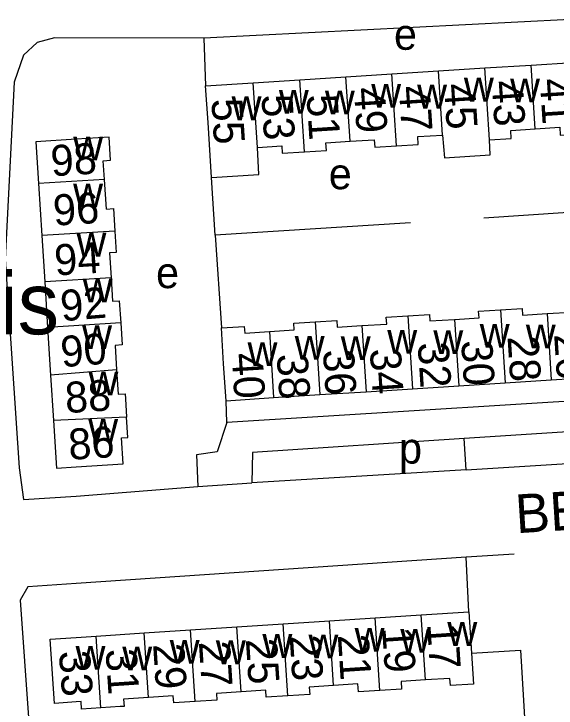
# Model space of a CAD drawing. Extents: x 159675 to 162108, y 386471 to 388472.
# Drawn here: x 160492 to 160562.1, y 387933.8 to 388023.5 of the extents above; entities that cross this region are included whole.
import ezdxf

# ---------------------------------------------------------------- set-up
doc = ezdxf.new("R2010")
doc.units = 0
for name, color, linetype in [('BLT_Basislijn', 7, 'Continuous'), ('BLT_Bebouwing', 7, 'Continuous'), ('BLT_Bebouwing_beschrifting', 7, 'Continuous'), ('BLT_Centroide', 7, 'Continuous'), ('BLT_Huisnummer', 7, 'Continuous'), ('BLT_Huisnummer_ tussenligend', 7, 'Continuous'), ('BLT_Onderverdeling_panden', 7, 'Continuous'), ('BLT_Straatnaam', 7, 'Continuous')]:
    doc.layers.add(name, color=color, linetype=linetype)

msp = doc.modelspace()

# ---------------------------------------------------------------- linework, layer by layer
at = {"layer": 'BLT_Basislijn'}
for p, q in [((160516.527, 388020.386), (160516.759, 388014.218)), ((160517.966, 387994.901), (160517.519, 388002.377)), ((160543.241, 387996.536), (160517.966, 387994.901)), ((160517.966, 387994.901), (160518.786, 387982.927)), ((160519.477, 387970.7), (160519.388, 387973.52)), ((160581.004, 387970.587), (160550.172, 387968.626)), ((160550.439, 387964.578), (160550.172, 387968.626)), ((160550.439, 387964.578), (160581.004, 387966.488)), ((160550.439, 387964.578), (160522.746, 387962.911)), ((160515.732, 387962.44), (160522.746, 387962.911)), ((160556.658, 387953.682), (160550.452, 387953.281)), ((160550.779, 387946.21), (160550.452, 387953.281))]:
    msp.add_line(p, q, dxfattribs=at)
for points in [[(160577.952, 388023.533), (160577.401, 388023.498), (160516.527, 388020.386)], [(160516.527, 388020.386), (160497.216, 388020.421), (160494.996, 388019.82), (160493.224, 388018.186), (160491.993, 388014.697), (160490.834, 387991.831), (160492.662, 387964.818), (160493.222, 387960.748), (160500, 387961.158), (160515.732, 387962.44)], [(160552.725, 387997.173), (160578.992, 387998.91), (160579.583, 387998.949)], [(160580.993, 387974.547), (160580.399, 387974.508), (160519.477, 387970.7)], [(160519.477, 387970.7), (160518.259, 387966.921), (160515.573, 387966.507), (160515.732, 387962.44)], [(160550.172, 387968.626), (160522.81, 387966.825), (160522.746, 387962.911)], [(160550.452, 387953.281), (160500, 387949.86), (160493.77, 387949.449), (160492.76, 387947.715), (160494.477, 387924.073), (160494.241, 387923.608)], [(160551.128, 387940.864), (160557.454, 387941.27), (160558.281, 387927.509), (160550.478, 387926.898)]]:
    msp.add_lwpolyline(points, dxfattribs=at)
at = {"layer": 'BLT_Bebouwing'}
for p, q in [((160552.855, 388016.538), (160558.834, 388016.923)), ((160558.834, 388016.923), (160564.804, 388017.306)), ((160540.829, 388015.765), (160546.842, 388016.152)), ((160546.842, 388016.152), (160552.855, 388016.538)), ((160522.918, 388014.614), (160528.924, 388015)), ((160528.924, 388015), (160534.896, 388015.384)), ((160534.896, 388015.384), (160540.829, 388015.765)), ((160516.759, 388014.218), (160522.918, 388014.614)), ((160495.156, 388001.594), (160495.577, 387994.868)), ((160503.921, 387998.297), (160503.682, 388002.125)), ((160495.577, 387994.868), (160495.953, 387988.879)), ((160495.953, 387988.879), (160496.321, 387982.998)), ((160496.321, 387982.998), (160496.709, 387976.796)), ((160496.709, 387976.796), (160497.075, 387970.957)), ((160561.438, 387976.211), (160567.393, 387976.592)), ((160543.497, 387975.063), (160549.47, 387975.445)), ((160549.47, 387975.445), (160555.459, 387975.828)), ((160555.459, 387975.828), (160561.438, 387976.211)), ((160531.522, 387974.297), (160537.505, 387974.679)), ((160537.505, 387974.679), (160543.497, 387975.063)), ((160519.388, 387973.52), (160525.549, 387973.914)), ((160525.549, 387973.914), (160531.522, 387974.297)), ((160538.681, 387945.424), (160544.624, 387945.81)), ((160544.624, 387945.81), (160550.779, 387946.21)), ((160550.779, 387946.21), (160551.128, 387940.864)), ((160526.793, 387944.651), (160532.747, 387945.038)), ((160532.747, 387945.038), (160538.681, 387945.424)), ((160514.817, 387943.872), (160520.801, 387944.261)), ((160520.801, 387944.261), (160526.793, 387944.651)), ((160502.612, 387943.079), (160508.812, 387943.482)), ((160508.812, 387943.482), (160514.817, 387943.872)), ((160500, 387942.909), (160502.612, 387943.079))]:
    msp.add_line(p, q, dxfattribs=at)
for points in [[(160517.519, 388002.377), (160517.061, 388009.508), (160516.759, 388014.218)], [(160553.45, 388007.252), (160556.266, 388007.433), (160556.2, 388008.46), (160559.364, 388008.663)], [(160559.364, 388008.663), (160562.528, 388008.866), (160562.593, 388007.853), (160565.399, 388008.033)], [(160541.426, 388006.467), (160544.243, 388006.648), (160544.178, 388007.657), (160547.374, 388007.862)], [(160547.374, 388007.862), (160547.616, 388004.915), (160553.527, 388005.296), (160553.45, 388007.252)], [(160503.682, 388002.125), (160503.531, 388004.549), (160504.469, 388004.607), (160504.282, 388007.598), (160500, 388007.331), (160494.817, 388007.009), (160495.156, 388001.594)], [(160529.521, 388005.697), (160532.374, 388005.88), (160532.311, 388006.858), (160535.429, 388007.058)], [(160535.429, 388007.058), (160538.548, 388007.258), (160538.61, 388006.286), (160541.426, 388006.467)], [(160517.519, 388002.377), (160523.643, 388002.77), (160523.454, 388006.266)], [(160523.454, 388006.266), (160526.608, 388006.469), (160526.669, 388005.514), (160529.521, 388005.697)], [(160503.921, 387998.297), (160504.853, 387998.355), (160505.034, 387995.458)], [(160505.034, 387995.458), (160505.207, 387992.685), (160504.337, 387992.631), (160504.538, 387989.413)], [(160504.538, 387989.413), (160504.726, 387986.395), (160505.598, 387986.449), (160505.777, 387983.587)], [(160554.856, 387985.257), (160557.669, 387985.437), (160557.725, 387984.568), (160560.89, 387984.77)], [(160560.89, 387984.77), (160564.056, 387984.973), (160563.999, 387985.856), (160566.788, 387986.034)], [(160536.958, 387983.226), (160540.158, 387983.431), (160540.102, 387984.303), (160542.895, 387984.481)], [(160542.895, 387984.481), (160545.688, 387984.66), (160545.742, 387983.825), (160548.92, 387984.028)], [(160548.92, 387984.028), (160552.098, 387984.232), (160552.044, 387985.077), (160554.856, 387985.257)], [(160505.777, 387983.587), (160505.955, 387980.726), (160505.048, 387980.669), (160505.246, 387977.504)], [(160525.002, 387982.463), (160528.193, 387982.667), (160528.138, 387983.523), (160530.921, 387983.701)], [(160530.921, 387983.701), (160533.704, 387983.879), (160533.759, 387983.022), (160536.958, 387983.226)], [(160518.786, 387982.927), (160521.757, 387983.117), (160521.812, 387982.259), (160525.002, 387982.463)], [(160519.388, 387973.52), (160519.083, 387978.287), (160518.786, 387982.927)], [(160505.246, 387977.504), (160505.443, 387974.34), (160506.354, 387974.397), (160506.395, 387973.74), (160506.543, 387971.367)], [(160497.075, 387970.957), (160497.46, 387964.812), (160500, 387964.971)], [(160500, 387964.971), (160506.077, 387965.35), (160505.869, 387968.697), (160506.707, 387968.749), (160506.543, 387971.367)], [(160500, 387934.562), (160497.205, 387934.379), (160496.663, 387942.69), (160500, 387942.909)], [(160551.128, 387940.864), (160551.388, 387936.882), (160548.388, 387936.686), (160548.327, 387937.612), (160545.171, 387937.406)], [(160539.292, 387936.052), (160536.506, 387935.871), (160536.44, 387936.894), (160533.29, 387936.689)], [(160545.171, 387937.406), (160542.015, 387937.201), (160542.078, 387936.234), (160539.292, 387936.052)], [(160527.399, 387935.362), (160524.595, 387935.179), (160524.536, 387936.085), (160521.346, 387935.877)], [(160533.29, 387936.689), (160530.141, 387936.484), (160530.203, 387935.545), (160527.399, 387935.362)], [(160509.354, 387935.144), (160506.143, 387934.935), (160506.204, 387933.995), (160505.711, 387933.963), (160503.216, 387933.8)], [(160515.419, 387934.622), (160512.625, 387934.44), (160512.565, 387935.353), (160509.354, 387935.144)], [(160521.346, 387935.877), (160518.157, 387935.67), (160518.213, 387934.804), (160515.419, 387934.622)], [(160503.216, 387933.8), (160500.721, 387933.638), (160500.658, 387934.604), (160500, 387934.562)]]:
    msp.add_lwpolyline(points, dxfattribs=at)
at = {"layer": 'BLT_Onderverdeling_panden'}
for p, q in [((160559.364, 388008.663), (160558.834, 388016.923)), ((160547.374, 388007.862), (160546.842, 388016.152)), ((160553.45, 388007.252), (160552.855, 388016.538)), ((160529.521, 388005.697), (160528.924, 388015)), ((160535.429, 388007.058), (160534.896, 388015.384)), ((160541.426, 388006.467), (160540.829, 388015.765)), ((160523.454, 388006.266), (160522.918, 388014.614)), ((160503.682, 388002.125), (160495.156, 388001.594)), ((160505.034, 387995.458), (160495.577, 387994.868)), ((160504.538, 387989.413), (160495.953, 387988.879)), ((160542.895, 387984.481), (160543.497, 387975.063)), ((160554.856, 387985.257), (160555.459, 387975.828)), ((160560.89, 387984.77), (160561.438, 387976.211)), ((160505.777, 387983.587), (160496.321, 387982.998)), ((160530.921, 387983.701), (160531.522, 387974.297)), ((160548.92, 387984.028), (160549.47, 387975.445)), ((160536.958, 387983.226), (160537.505, 387974.679)), ((160525.002, 387982.463), (160525.549, 387973.914)), ((160505.246, 387977.504), (160496.709, 387976.796)), ((160506.543, 387971.367), (160497.075, 387970.957)), ((160545.171, 387937.406), (160544.624, 387945.81)), ((160533.29, 387936.689), (160532.747, 387945.038)), ((160539.292, 387936.052), (160538.681, 387945.424)), ((160521.346, 387935.877), (160520.801, 387944.261)), ((160527.399, 387935.362), (160526.793, 387944.651)), ((160509.354, 387935.144), (160508.812, 387943.482)), ((160515.419, 387934.622), (160514.817, 387943.872)), ((160503.216, 387933.8), (160502.612, 387943.079))]:
    msp.add_line(p, q, dxfattribs=at)

# ---------------------------------------------------------------- texts
at = {"layer": 'BLT_Bebouwing_beschrifting'}
msp.add_text('Gemeenschapshuis', height=8, dxfattribs=at).set_placement((160403.262, 387982.102))
at = {"layer": 'BLT_Centroide'}
for s, p in [('e', (160541.101, 388018.891)), ('w', (160550.141, 388012.203)), ('w', (160556.109, 388012.094)), ('w', (160538.156, 388011.406)), ('w', (160544.094, 388011.297)), ('w', (160526.219, 388010.625)), ('w', (160532.172, 388010.547)), ('w', (160520.109, 388009.781)), ('w', (160499.633, 388004.594)), ('e', (160532.669, 388000.86)), ('w', (160499.625, 387998.5)), ('w', (160500.055, 387992.156)), ('e', (160510.346, 387988.068)), ('w', (160500.867, 387986.219)), ('w', (160500.789, 387980.188)), ('w', (160540.234, 387979.578)), ('w', (160546.188, 387979.547)), ('w', (160552.188, 387980.359)), ('w', (160558.141, 387980.297)), ('w', (160528.266, 387978.812)), ('w', (160534.219, 387978.766)), ('w', (160522.172, 387977.984)), ('w', (160501.617, 387974.219)), ('w', (160501.578, 387968.094)), ('p', (160541.752, 387965.383)), ('w', (160536.016, 387941.062)), ('w', (160541.922, 387940.922)), ('w', (160548, 387941.812)), ('w', (160524.094, 387940.266)), ('w', (160530.047, 387940.203)), ('w', (160512.109, 387939.5)), ('w', (160518.078, 387939.438)), ('w', (160499.938, 387938.734)), ('w', (160505.984, 387938.641))]:
    msp.add_text(s, height=4, dxfattribs=at).set_placement(p)
at = {"layer": 'BLT_Huisnummer'}
for s, height, rotation, p in [('41', 4, 273.67377, (160559.946, 388015.092)), ('45', 3.9999, 273.66287, (160547.562, 388014.425)), ('49', 4, 273.67375, (160535.913, 388013.94)), ('55', 4, 273.67197, (160517.489, 388012.492)), ('98', 4, 3.57143, (160496.846, 388002.527)), ('94', 4, 3.56219, (160497.315, 387989.693)), ('90', 4, 4.74142, (160498.169, 387977.831)), ('26', 4, 273.66651, (160561.799, 387982.098)), ('30', 4, 273.66188, (160549.784, 387981.262)), ('34', 4, 273.65674, (160537.977, 387980.18)), ('40', 4, 273.66243, (160520.107, 387979.589)), ('86', 4, 3.5687, (160499.128, 387965.862)), ('17', 4, 273.73007, (160545.371, 387944.642)), ('21', 4, 273.7326, (160533.83, 387943.203)), ('25', 4, 273.72362, (160521.944, 387942.672)), ('29', 4, 273.7192, (160509.961, 387942.023)), ('33', 4, 274.50556, (160497.767, 387941.073))]:
    msp.add_text(s, height=height, rotation=rotation, dxfattribs=at).set_placement(p)
at = {"layer": 'BLT_Huisnummer_ tussenligend'}
for s, height, rotation, p in [('47', 3.9999, 273.66287, (160541.722, 388014.14)), ('43', 3.9999, 273.67185, (160553.733, 388014.818)), ('53', 4, 273.67197, (160523.961, 388013.033)), ('51', 4, 273.67375, (160529.798, 388013.041)), ('96', 4, 3.56219, (160497.153, 387996.14)), ('92', 4, 4.74142, (160498.138, 387983.781)), ('28', 4, 273.66651, (160555.771, 387981.798)), ('32', 4, 273.66188, (160544.163, 387980.981)), ('36', 4, 273.66103, (160531.911, 387980.046)), ('38', 4, 273.66243, (160525.94, 387979.504)), ('88', 4, 3.5687, (160498.689, 387971.907)), ('19', 3.9999, 273.72115, (160539.561, 387944.15)), ('27', 4, 273.7192, (160515.871, 387942.329)), ('23', 4, 273.71927, (160527.605, 387943.115)), ('31', 4, 273.73125, (160503.819, 387941.338))]:
    msp.add_text(s, height=height, rotation=rotation, dxfattribs=at).set_placement(p)
at = {"layer": 'BLT_Straatnaam'}
msp.add_text('BEIJERLANDLAAN', height=5, rotation=3.61283, dxfattribs=at).set_placement((160556.941, 387956.372))

doc.saveas('drawing.dxf')
